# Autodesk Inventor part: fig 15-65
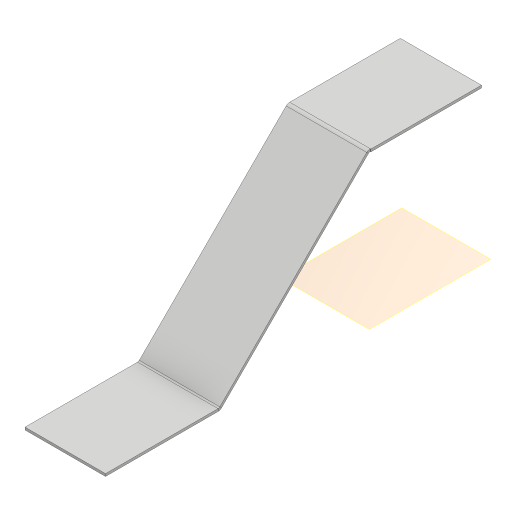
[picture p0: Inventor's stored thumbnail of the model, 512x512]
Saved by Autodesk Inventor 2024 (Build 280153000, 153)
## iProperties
Created: 2015-07
Part Number: fig 15-65
Material: Generic
Document SubType Name: Sheet Metal
Designer: Sandeep
Density: 1 g/cm^3
Sheet Metal Rule: Default_mm
Appearance: Default
Author: Sandeep
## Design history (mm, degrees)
sketch "Sketch1"
  geometry: L1 (0, 0)-(16.327, 0); L2 (16.327, 0)-(16.327, 22.261); L3 (16.327, 22.261)-(0, 22.261); L4 (0, 22.261)-(0, 0)
  constraints: 8 end point, 2 parallel, 1 horizontal, 1 perpendicular
workplane "Work Plane1"
sketch "Sketch2"
  geometry: L1 (0, -53.275)-(16.202, -53.275); L2 (16.202, -53.275)-(16.202, -30.325); L3 (16.202, -30.325)-(0, -30.325); L4 (0, -30.325)-(0, -53.275); 1 further point
  constraints: 8 end point, 2 parallel, 1 horizontal, 1 perpendicular
node "Face1"
node "Face2"
bend "Bend2" dims "d7" = 0.5 (= BendReliefWidth), "d8" = 0.25 (= BendReliefDepth), "d9" = 1 (= MinimumRemnant), "d10" = 0.5 (= BendRadius), "d11" = 0.5 (= BendRadius), "d12" = 0.5 (= Thickness), "SeamGap" = 0.01
body "Solid1"
face "Plate1" dims "d12" = 0.5 (= Thickness)
face "Plate2" dims "d2" = 0.5 (= BendRadius), "d3" = 0.5 (= BendReliefWidth), "d5" = 1 (= MinimumRemnant), "d12" = 0.5 (= Thickness)
bend "Bend1" dims "d2" = 0.5 (= BendRadius), "d3" = 0.5 (= BendReliefWidth), "d4" = 0.25 (= BendReliefDepth), "d5" = 1 (= MinimumRemnant), "d6" = 0.5 (= BendRadius), "d12" = 0.5 (= Thickness), "SeamGap" = 0.01
other parameters: "Thickness" = 0.5, "BendRadius" = 0.5 (= Thickness), "BendReliefWidth" = 0.5 (= Thickness), "BendReliefDepth" = 0.25 (= 0.5 x Thickness), "CornerReliefSize" = 2 (= 4 x Thickness), "MinimumRemnant" = 1 (= 2 x Thickness), "TransitionRadius" = 0.5 (= BendRadius), "JacobiRadiusSize" = 0.5 (= BendRadius), "GapSize" = 0.5 (= Thickness), "d1" = 0.5 (= BendRadius)
